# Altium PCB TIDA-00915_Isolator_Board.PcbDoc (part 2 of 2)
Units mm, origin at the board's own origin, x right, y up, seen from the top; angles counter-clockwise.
Board outline 80 x 46 mm, 4 copper layers (Top Layer, L2, L3, Bottom Layer), stack 0.8 mm thick; 132 components, 79 nets, 362 pads, 253 vias.
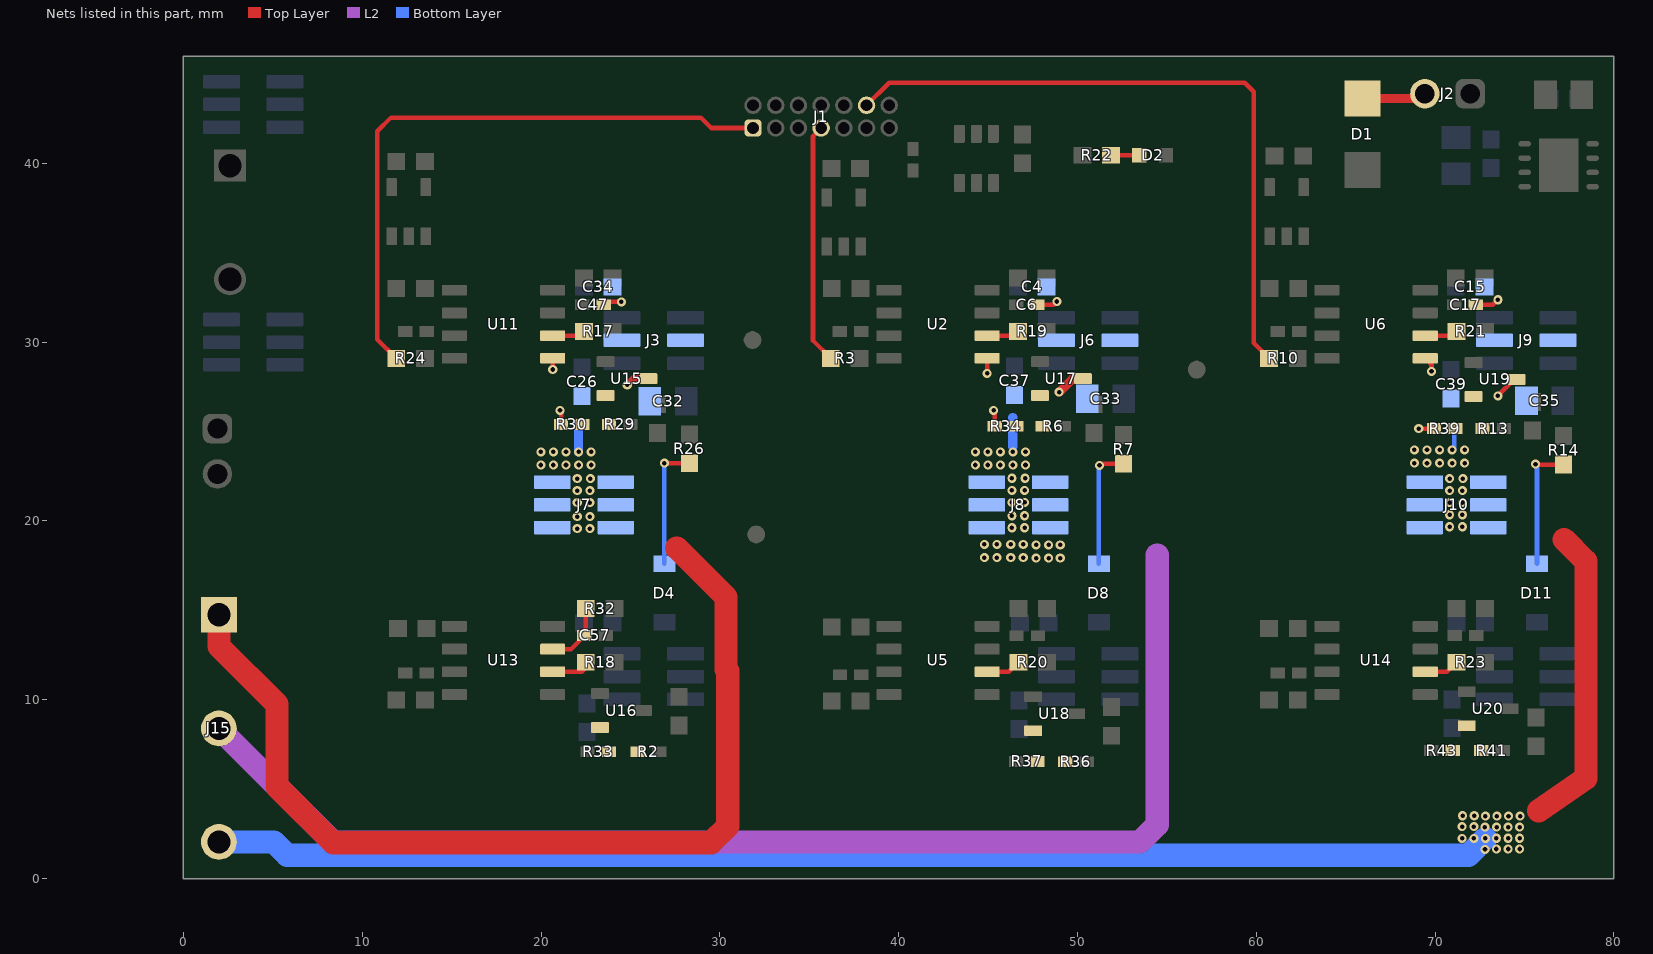
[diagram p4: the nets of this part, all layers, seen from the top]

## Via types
v1: diameter 0.508, hole 0.254, Top Layer to Bottom Layer, 248 vias
v2: diameter 0.5, hole 0.2, Top Layer to Bottom Layer, 5 vias

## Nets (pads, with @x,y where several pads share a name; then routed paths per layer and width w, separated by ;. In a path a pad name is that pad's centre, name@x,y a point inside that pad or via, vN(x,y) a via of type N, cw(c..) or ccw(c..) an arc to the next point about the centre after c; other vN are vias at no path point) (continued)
NetC57_1: C57.1 R32.1 U13.7 | length 3.6
  Top Layer w0.254: U13.7@20.65,12.835 21.672,12.835 22.5,13.663 R32.1@22.5,15.1
NetD1_2: D1.2 J2.2 | length 3.6
  Top Layer w0.508: D1.2@65.938,43.624 69.154,43.624 J2.2@69.43,43.9
NetD2_1: D2.1 R22.1 | length 1.6
  Top Layer w0.254: R22.1@51.879,40.456 D2.1@53.454,40.456
NetD4_1: D4.1 R26.1 | length 7
  Top Layer w0.254: v1(26.899,23.234) 26.905,23.228 R26.1@28.296,23.228
  Bottom Layer w0.254: D4.1@26.899,17.608 v1(26.899,23.234)
NetD8_1: D8.1 R7.1 | length 6.9
  Top Layer w0.254: v1(51.232,23.107) 51.327,23.203 R7.1@52.578,23.203
  Bottom Layer w0.254: D8.1@51.2,17.608 51.2,23.076 v1(51.232,23.107)
NetD11_1: D11.1 R14.1 | length 7.2
  Top Layer w0.254: v1@75.632,23.2 v1(75.616,23.184) ccw(c75.647,23.184) 75.647,23.152 R14.1@77.191,23.152
  Bottom Layer w0.254: v1(75.616,23.184) 75.7,23.099 D11.1@75.7,17.607
NetR2_1: R2.1 R33.2 U16.2
NetR6_1: R6.1 R34.2 U17.2
NetR13_1: R13.1 R39.2 U19.2
NetR17_1: R17.1 U11.6 | length 1.8
  Top Layer w0.254: U11.6@20.65,30.365 22.165,30.365 R17.1@22.4,30.6
NetR18_1: R18.1 U13.6 | length 2.4
  Top Layer w0.254: U13.6@20.65,11.565 22.265,11.565 R18.1@22.8,12.1
NetR19_1: R19.1 U2.6 | length 1.8
  Top Layer w0.254: U2.6@44.95,30.365 46.438,30.365 R19.1@46.673,30.6
NetR20_1: R20.1 U5.6 | length 2
  Top Layer w0.254: U5.6@44.95,11.565 46.165,11.565 R20.1@46.7,12.1
NetR21_1: R21.1 U6.6 | length 1.8
  Top Layer w0.254: U6.6@69.45,30.365 70.965,30.365 R21.1@71.2,30.6
NetR23_1: R23.1 U14.6 | length 2
  Top Layer w0.254: U14.6@69.45,11.565 70.665,11.565 R23.1@71.2,12.1
NetR29_1: R29.1 R30.2 U15.2
NetR36_1: R36.1 R37.2 U18.2
NetR41_1: R41.1 R43.2 U20.2
PHASEU: C26.2 C32.2 C34.2 C47.2 J3.3 J3.4 J7.1 J7.2 J7.3 J7.4 J7.5 J7.6 J15.1 R30.1 U11.5 U15.3 | length 60
  Top Layer w0.254: v1(20.65,28.474) U11.5@20.65,29.095 ; v1(21.057,26.187) 21.117,26.127 R30.1@21.117,25.4 ; C47.2@23.5,32.1 23.658,32.258 v1(24.486,32.258)
  Top Layer w0.4: v1(24.82,27.616) 25.169,27.965 U15.3@26,27.965
  Top Layer w1.3: J15.1@1.981,14.75 1.981,12.996 5.231,9.746 5.231,5.15 8.381,2 29.5,2 30.436,2.936 30.436,11.605 30.347,11.694 30.347,15.733 27.584,18.495
  Bottom Layer w0.508: v1(22.095,23.869) 22.095,25.473
  other v1: 22.022,19.577 22.733,19.577 22.022,20.25 22.733,20.25 22.022,21.025 22.733,21.025 22.022,21.698 22.733,21.698 22.022,22.371 22.758,22.371 19.99,23.133 20.691,23.133 21.393,23.133 22.095,23.133 22.796,23.133 19.99,23.869 20.691,23.869 21.393,23.869 22.796,23.869
PHASEV: C4.2 C6.2 C33.2 C37.2 J6.3 J6.4 J8.1 J8.2 J8.3 J8.4 J8.5 J8.6 J15.2 R34.1 U2.5 U17.3 | length 76.8
  Top Layer w0.254: U2.5@44.933,29.095 U2.5@44.95,29.095 v1(44.95,28.259) ; v1(45.314,26.187) 45.374,26.127 R34.1@45.374,25.298 ; C6.2@47.768,32.1 48.667,32.1 v1(48.844,32.277)
  Top Layer w0.5: v1(48.971,27.203) 49.733,27.965 U17.3@50.3,27.965
  L2 w1.3: J15.2@1.981,8.4 8.331,2.05 53.5,2.05 54.458,3.008 54.458,18.104
  Bottom Layer w0.508: 46.377,24.174 46.377,25.778
  other v1: 47.688,17.926 48.39,17.926 49.035,17.926 44.793,17.951 45.495,17.951 46.266,17.951 46.968,17.951 47.688,18.662 48.39,18.662 49.035,18.662 44.793,18.688 45.495,18.688 46.266,18.688 46.968,18.688 46.33,19.621 47.041,19.621 46.33,20.295 47.041,20.295 46.33,21.044 47.041,21.044 46.33,21.717 47.041,21.717 46.33,22.39 47.066,22.39 44.285,23.133 44.987,23.133 45.688,23.133 46.39,23.133 47.092,23.133 44.285,23.869 44.987,23.869 45.688,23.869 46.39,23.869 47.092,23.869
PHASEW: C15.2 C17.2 C35.2 C39.2 J9.3 J9.4 J10.1 J10.2 J10.3 J10.4 J10.5 J10.6 J15.3 R39.1 U6.5 U19.3 | length 94.2
  Top Layer w0.254: v1(69.088,25.171) R39.1@69.936,25.171 ; U6.5@69.45,29.095 69.799,28.746 v1(69.799,28.372) ; C17.2@72.279,32.1 73.233,32.1 v1(73.508,32.375) ; v1(73.508,27) 74.422,27.915 U19.3@74.555,27.915
  Top Layer w1.3: 75.8,3.8 78.435,5.607 78.435,17.748 77.216,18.967
  Bottom Layer w0.254: v1@71.079,23.971 71.079,25.124
  Bottom Layer w1.3: J15.3@1.981,2.05 5.05,2.05 5.8,1.3 71.87,1.3 v1(72.816,2.246)
  other v1: 72.791,1.637 73.432,1.656 74.082,1.656 74.732,1.656 71.516,2.246 72.166,2.246 73.432,2.256 74.082,2.256 74.732,2.256 72.786,2.881 73.436,2.881 74.082,2.881 74.732,2.881 71.516,2.907 72.166,2.907 72.812,3.491 73.462,3.491 74.107,3.491 74.757,3.491 71.542,3.516 72.192,3.516 70.815,19.678 71.526,19.678 70.815,20.352 71.526,20.352 70.815,21.025 71.526,21.025 70.815,21.698 71.526,21.698 70.815,22.371 71.552,22.371 68.847,23.241 69.548,23.241 70.25,23.241 70.952,23.241 71.653,23.241 68.847,23.978 69.548,23.978 70.25,23.978 70.952,23.978 71.653,23.978
Top_FET_U: J1.1 R24.1 | length 34.7
  Top Layer w0.254: R24.1@11.9,29.1 10.846,30.154 10.846,41.802 11.608,42.564 28.931,42.564 29.515,41.98 J1.1@31.852,41.98
Top_FET_V: J1.7 R3.1 | length 13.5
  Top Layer w0.254: J1.7@35.662,41.98 35.208,41.526 35.208,30.092 R3.1@36.2,29.1
Top_FET_W: J1.12 R10.1 | length 37.7
  Top Layer w0.254: J1.12@38.202,43.25 39.472,44.52 59.36,44.52 59.863,44.016 59.863,29.956 R10.1@60.719,29.1
pads on no net: FID1.1 FID2.1 FID3.1

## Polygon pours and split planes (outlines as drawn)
PHASEW on Bottom Layer "BOTTOM_LAYER_PHASEW_P072" (solid, remove dead copper, pour order 72): 68.783,24.835 ccw(c68.961,24.835) 68.961,24.657 77.47,24.657 ccw(c77.47,24.835) 77.648,24.835 77.622,25.47 77.622,34.055 ccw(c77.47,34.055) 77.47,34.207 69.113,34.207 ccw(c69.113,33.877) 68.783,33.877
PHASEV on Bottom Layer "BOTTOM_LAYER_PHASEV_P068" (solid, remove dead copper, pour order 68): 44.348,24.758 ccw(c44.526,24.758) 44.526,24.581 53.035,24.581 ccw(c53.035,24.758) 53.213,24.758 53.188,25.393 53.188,33.979 ccw(c53.035,33.979) 53.035,34.131 44.679,34.131 ccw(c44.679,33.801) 44.348,33.801
PHASEU on Bottom Layer "BOTTOM_LAYER_PHASEU_P066" (solid, remove dead copper, pour order 66): 20.168,24.809 ccw(c20.345,24.809) 20.345,24.631 28.854,24.631 ccw(c28.854,24.809) 29.032,24.809 29.007,25.444 29.007,34.029 ccw(c28.854,34.029) 28.854,34.182 20.498,34.182 ccw(c20.498,33.852) 20.168,33.852
PHASEW on Bottom Layer "BOTTOM_LAYER_PHASEW_P056" (solid, remove dead copper, pour order 56): 74.306,22.301 ccw(c74.061,22.301) 74.061,22.546 72.125,22.546 cw(c72.125,22.597) 72.074,22.597 72.074,24.248 ccw(c71.896,24.248) 71.896,24.426 68.721,24.426 ccw(c68.717,24.218) 68.509,24.222 68.509,19.672 ccw(c68.909,19.672) 68.909,19.272 74.109,19.272 ccw(c74.109,19.473) 74.309,19.473 74.309,22.267 ccw(c74.131,22.267)
PHASEV on Bottom Layer "BOTTOM_LAYER_PHASEV_P048" (solid, remove dead copper, pour order 48): 44.063,24.428 ccw(c44.063,24.205) 43.84,24.205 43.84,19.434 ccw(c43.997,19.438) 44.001,19.282 ccw(c44.079,19.675) 44.079,19.275 49.279,19.275 ccw(c49.279,19.475) 49.479,19.475 49.479,22.269 ccw(c49.302,22.269) 49.476,22.304 ccw(c49.231,22.304) 49.231,22.549 47.295,22.549 cw(c47.295,22.599) 47.244,22.599 47.244,24.25 ccw(c47.066,24.25) 47.066,24.428
PHASEU on Bottom Layer "BOTTOM_LAYER_PHASEU_P008" (solid, remove dead copper, pour order 8): 25.397,22.329 ccw(c25.152,22.329) 25.152,22.574 23.216,22.574 cw(c23.216,22.625) 23.165,22.625 23.165,24.276 ccw(c22.987,24.276) 22.987,24.454 19.812,24.454 ccw(c19.808,24.246) 19.6,24.25 19.6,19.7 ccw(c20,19.7) 20,19.3 25.199,19.3 ccw(c25.199,19.501) 25.4,19.501 25.4,22.295 ccw(c25.222,22.295)
HVBUS_RTN on Bottom Layer "BOTTOM_LAYER_HVBUS_RTN_P000" (solid, remove dead copper, pour order 0): 19.9,7.274 19.9,4.8 ccw(c20.1,4.8) 20.1,4.6 25.7,4.6 ccw(c25.7,5) 26.1,5 26.1,6.788 ccw(c25.903,6.8) 26.1,6.8 26.1,10.4 cw(c26.4,10.4) 26.4,10.7 28.7,10.7 ccw(c28.7,11) 29,11 29,14.9 ccw(c28.5,14.9) 28.5,15.4 23.3,15.4 cw(c23.3,15.7) 23,15.7 23,15.8 ccw(c22.9,15.8) 22.9,15.9 20.2,15.9 ccw(c20.2,15.6) 19.9,15.6 19.9,7.3 ccw(c20.609,7.3)
HVBUS_RTN on Bottom Layer "BOTTOM_LAYER_HVBUS_RTN_P036" (solid, remove dead copper, pour order 36): 44.157,3.847 ccw(c44.2,3.847) 44.2,3.804 50.004,3.804 ccw(c50.004,4.2) 50.4,4.2 50.4,10.57 cw(c50.657,10.57) 50.657,10.827 52.957,10.827 ccw(c52.957,11.127) 53.257,11.127 53.257,15.027 ccw(c52.757,15.027) 52.757,15.527 47.557,15.527 cw(c47.557,15.827) 47.257,15.827 47.257,15.927 ccw(c47.157,15.927) 47.157,16.027 44.457,16.027 ccw(c44.457,15.727) 44.157,15.727
5V on Bottom Layer "BOTTOM_LAYER_5V_P080" (solid, remove dead copper, pour order 80): 66.827,39.871 66.827,38.728 ccw(c67.119,38.741) 67.132,38.449 74.273,38.449 ccw(c74.273,38.855) 74.68,38.855 74.68,40.065 ccw(c74.597,40.065) 74.597,40.148 67.104,40.148 ccw(c67.104,39.871)
PHASEW on Bottom Layer "BOTTOM_LAYER_PHASEW_P086" (solid, remove dead copper, pour order 86): 76.179,4.567 ccw(c75.773,4.567) 75.773,4.974 70.795,4.974 ccw(c70.795,4.669) 70.49,4.669 70.49,1.722 ccw(c70.871,1.722) 70.871,1.341 75.824,1.341 ccw(c75.824,1.697) 76.179,1.697
HVBUS on Bottom Layer "BOTTOM_LAYER_HVBUS_P088" (solid, remove dead copper, pour order 88): 6.323,33.917 6.323,34.387 ccw(c6.02,34.387) 6.02,34.69 1.219,34.69 ccw(c1.219,34.436) 0.965,34.436 0.965,28.767 ccw(c1.313,28.772) 1.318,28.424 ccw(c1.397,28.822) 1.397,28.416 6.045,28.416 ccw(c6.045,28.695) 6.325,28.695 6.325,33.877 ccw(c5.918,33.877)
HVBUS_RTN on Bottom Layer "BOTTOM_LAYER_HVBUS_RTN_P090" (solid, remove dead copper, pour order 90): 6.399,44.255 6.399,44.725 ccw(c6.096,44.725) 6.096,45.028 1.295,45.028 ccw(c1.295,44.774) 1.041,44.774 1.041,39.105 ccw(c1.389,39.109) 1.394,38.762 ccw(c1.473,39.16) 1.473,38.754 6.121,38.754 ccw(c6.121,39.033) 6.401,39.033 6.401,44.215 ccw(c5.995,44.215)
GND on Bottom Layer "BOTTOM_LAYER_GND_P092" (solid, remove dead copper, pour order 92): 64,9.2 ccw(c64,9.5) 64.3,9.5 64.3,38.648 cw(c64.442,38.637) 64.452,38.779 65.557,38.779 ccw(c65.557,38.957) 65.735,38.957 65.735,40.735 cw(c66.4,40.735) 66.4,41.4 74.5,41.4 cw(c74.5,40.9) 75,40.9 75,38.6 ccw(c75.6,38.6) 75.6,38 79.1,38 ccw(c79.1,38.2) 79.3,38.2 79.3,44.8 ccw(c78.9,44.8) 78.9,45.2 11.9,45.2 ccw(c11.9,44.5) 11.2,44.5 11.2,25.8 cw(c10.9,25.8) 10.9,25.5 10,25.5 ccw(c10,25) 9.5,25 9.5,9.6 ccw(c9.9,9.6) 9.9,9.2 15.3,9.2 ccw(c15.3,9.5) 15.6,9.5 15.6,37.918 cw(c15.969,37.918) 15.969,38.287 33.245,38.287 cw(c33.245,38.011) 33.521,38.011 33.521,9.479 ccw(c33.9,9.479) 33.9,9.1 39.4,9.1 ccw(c39.4,9.5) 39.8,9.5 39.8,37.8 cw(c40.4,37.8) 40.4,38.4 58.087,38.4 cw(c58.087,38.072) 58.415,38.072 58.415,9.785 ccw(c59,9.785) 59,9.2
HVBUS_RTN on Bottom Layer "BOTTOM_LAYER_HVBUS_RTN_P096" (solid, remove dead copper, pour order 96): 68.7,15.7 cw(c69,15.7) 69,16 71.7,16 cw(c71.7,15.9) 71.8,15.9 71.8,15.8 ccw(c72.1,15.8) 72.1,15.5 77.3,15.5 cw(c77.3,15) 77.8,15 77.8,11.1 cw(c77.5,11.1) 77.5,10.8 75.2,10.8 ccw(c75.2,10.5) 74.9,10.5 74.9,6.9 cw(c74.7,6.9) 74.7,6.7 69.4,6.7 cw(c69.4,7.4) 68.7,7.4
12V on L3 "L3_12V_P054" (solid, remove dead copper, pour order 54): 70.307,6.393 ccw(c70.9,6.393) 70.9,5.8 76.2,5.8 ccw(c76.2,6.5) 76.9,6.5 76.9,14.528 ccw(c76.452,14.522) 76.447,14.97 ccw(c76.352,14.497) 76.352,14.979 70.637,14.979 ccw(c70.637,14.649) 70.307,14.649
12V on L3 "L3_12V_P038" (solid, remove dead copper, pour order 38): 46.024,1.976 ccw(c46.3,1.976) 46.3,1.7 52.2,1.7 ccw(c52.2,2) 52.5,2 52.5,14.899 ccw(c52.17,14.894) 52.164,15.224 ccw(c52.07,14.751) 52.07,15.233 46.354,15.233 ccw(c46.354,14.903) 46.024,14.903
12V on L3 "L3_12V_P040" (solid, remove dead copper, pour order 40): 22.115,6.9 ccw(c22.503,6.901) 22.504,6.513 ccw(c22.497,6.717) 22.522,6.514 28.034,6.514 ccw(c28.034,7.124) 28.644,7.124 28.644,14.49 ccw(c28.161,14.49) 28.161,14.973 22.445,14.973 ccw(c22.445,14.642) 22.115,14.642
5V on L3 "L3_5V_P082" (solid, pour order 82): 33.909,43.097 ccw(c34.239,43.097) 34.239,42.767 35.814,42.767 ccw(c35.814,43.097) 36.144,43.097 36.144,44.697 ccw(c36.017,44.697) 36.017,44.824 34.188,44.824 ccw(c34.188,44.545) 33.909,44.545
HVBUS_RTN on L3 "L3_HVBUS_RTN_P094" (solid, remove dead copper, pour order 94): 19.9,8 19.9,4.788 ccw(c20.088,4.788) 20.088,4.6 25.7,4.6 ccw(c25.7,5) 26.1,5 26.1,5.8 ccw(c26,5.8) 26,5.9 21.9,5.9 cw(c21.9,6.1) 21.7,6.1 21.7,8.2 ccw(c21.5,8.2) 21.5,8.4 20.3,8.4 ccw(c20.3,8)
5V_H_W on L2 "L2_5V_H_W_P074" (solid, remove dead copper, pour order 74): 69.151,34.048 68.897,34.048 ccw(c68.897,33.934) 68.783,33.934 68.783,24.799 ccw(c68.926,24.799) 68.926,24.657 76.339,24.657 ccw(c76.339,24.816) 76.498,24.816 76.498,27.534 ccw(c76.312,27.534) 76.312,27.721 74.049,27.721 cw(c74.049,27.915) 73.855,27.915 73.855,30.615 ccw(c73.562,30.612) 73.558,30.905 70.923,30.905 cw(c70.923,31.166) 70.663,31.166 70.663,33.922 ccw(c70.53,33.922) 70.53,34.055 69.215,34.055 ccw(c69.215,33.725)
5V_H_V on L2 "L2_5V_H_V_P070" (solid, remove dead copper, pour order 70): 51.885,27.464 ccw(c51.587,27.464) 51.587,27.762 49.61,27.762 cw(c49.61,27.97) 49.403,27.97 49.403,30.829 ccw(c49.251,30.829) 49.251,30.981 46.438,30.981 cw(c46.438,31.242) 46.177,31.242 46.177,33.998 ccw(c46.044,33.998) 46.044,34.131 44.729,34.131 ccw(c44.729,33.801) 44.399,33.801 44.399,24.79 ccw(c44.628,24.79) 44.628,24.562 51.581,24.562 ccw(c51.581,24.867) 51.885,24.867
5V_H_U on L2 "L2_5V_H_U_P064" (solid, remove dead copper, pour order 64): 20.168,24.774 ccw(c20.31,24.774) 20.31,24.631 26.631,24.631 ccw(c26.631,25.2) 27.2,25.2 27.2,28 ccw(c26.9,28) 26.9,28.3 25.4,28.3 cw(c25.386,28.514) 25.171,28.5 25.171,30.88 ccw(c25.019,30.88) 25.019,31.032 22.206,31.032 cw(c22.206,31.293) 21.946,31.293 21.946,34.049 ccw(c21.813,34.049) 21.813,34.182 20.498,34.182 ccw(c20.498,33.852) 20.168,33.852
5V_L_W on L2 "L2_5V_L_W_P052" (solid, remove dead copper, pour order 52): 69.105,15.405 68.822,15.405 ccw(c68.822,15.283) 68.7,15.283 68.7,7.148 ccw(c69.068,7.148) 69.068,6.78 76.147,6.78 ccw(c76.147,7.264) 76.632,7.264 76.632,10.922 ccw(c76.251,10.922) 76.251,11.303 72.454,11.303 cw(c72.454,11.589) 72.168,11.589 72.168,15.227 ccw(c71.984,15.227) 71.984,15.411 69.164,15.411 ccw(c69.164,15.106)
5V_L_U on L2 "L2_5V_L_U_P004" (solid, remove dead copper, pour order 4): 19.9,8.72 ccw(c20.22,8.72) 20.22,8.4 22.85,8.4 cw(c22.85,8.2) 23.05,8.2 23.05,6.8 ccw(c23.3,6.8) 23.3,6.55 27.95,6.55 ccw(c27.95,6.9) 28.3,6.9 28.3,11.3 ccw(c28.1,11.3) 28.1,11.5 23.525,11.5 cw(c23.525,11.625) 23.4,11.625 23.4,15.7 ccw(c23.2,15.7) 23.2,15.9 20.2,15.9 ccw(c20.2,15.6) 19.9,15.6
3V3 on L2 "L2_3V3_P010" (solid, pour order 10): 58.42,22.497 ccw(c59.029,22.497) 59.029,21.888 60.96,21.888 cw(c60.96,21.177) 61.671,21.177 61.671,15.143 ccw(c62.381,15.156) 62.394,14.446 63.373,14.446 ccw(c63.373,15.03) 63.957,15.03 63.957,38.215 cw(c64.344,38.215) 64.344,38.601 65.405,38.601 ccw(c65.392,38.944) 65.735,38.957 65.735,40.684 cw(c65.989,40.684) 65.989,40.938 70.409,40.938 cw(c70.409,40.659) 70.688,40.659 70.688,39.059 ccw(c71.145,39.059) 71.145,38.601 79.258,38.601 ccw(c79.258,38.795) 79.451,38.795 79.451,45.002 ccw(c79.299,45.002) 79.299,45.155 9.627,45.155 ccw(c9.627,44.977) 9.449,44.977 9.449,44.306 9.449,42.214 ccw(c9.872,42.21) 9.449,42.208 9.449,16.021 9.449,14.446 ccw(c10.262,14.446) 10.262,13.633 15.043,13.633 ccw(c15.043,14.262) 15.672,14.262 15.672,37.925 cw(c16.041,37.925) 16.041,38.294 cw(c16.1,38.003) 16.1,38.3 33.169,38.3 cw(c33.169,37.941) 33.528,37.941 33.528,14.09 ccw(c34.214,14.09) 34.214,13.405 39.192,13.405 ccw(c39.19,14.215) 40,14.217 40,38.1 cw(c40.2,38.1) 40.2,38.3 58.137,38.3 cw(c58.137,38.017) 58.42,38.017
5V_L_V on L2 "L2_5V_L_V_P042" (solid, remove dead copper, pour order 42): 51.664,5.69 ccw(c51.664,5.994) 51.968,5.994 51.968,11.252 ccw(c51.689,11.252) 51.689,11.532 47.867,11.532 cw(c47.867,11.69) 47.708,11.69 47.708,15.328 ccw(c47.523,15.328) 47.523,15.513 44.704,15.513 ccw(c44.704,15.209) 44.645,15.507 ccw(c44.641,15.062) 44.196,15.065 44.196,6.198 ccw(c44.704,6.198) 44.704,5.69
PHASEV on L2 "L2_PHASEV_P046" (solid, remove dead copper, pour order 46): 44.171,17.907 ccw(c44.527,17.907) 44.527,17.551 44.806,17.552 45.716,17.553 ccw(c45.775,17.847) 45.775,17.548 54.614,17.548 ccw(c54.614,17.827) 54.669,17.553 ccw(c54.672,17.999) 55.118,17.996 55.118,19.431 ccw(c54.635,19.431) 54.635,19.914 49.784,19.914 cw(c49.784,20.066) 49.632,20.066 49.632,22.443 ccw(c49.5,22.443) 49.5,22.574 44.545,22.574 ccw(c44.545,22.2) 44.171,22.2
NetR41_1 on Top Layer "TOP_LAYER_NETR41_1_P110" (solid, remove dead copper, pour order 110): 71.612,8.757 ccw(c71.612,8.478) 71.333,8.478 71.323,8.452 71.323,7.493 cw(c71.196,7.493) 71.196,7.366 70.887,7.366 ccw(c70.887,7.163) 70.683,7.163 70.683,7.013 ccw(c70.833,7.013) 70.833,6.863 72.68,6.863 ccw(c72.68,7.01) 72.827,7.01 72.827,7.362 ccw(c72.727,7.362) 72.727,7.463 72.446,7.463 cw(c72.446,7.722) 72.187,7.722 72.187,8.539 ccw(c71.969,8.539) 71.969,8.757
NetR13_1 on Top Layer "TOP_LAYER_NETR13_1_P108" (solid, remove dead copper, pour order 108): 70.663,25.451 70.663,24.816 70.739,24.74 73.076,24.74 73.127,24.79 73.127,25.527 73.076,25.578 72.949,25.578 72.746,25.781 72.746,27.254 72.644,27.356 71.704,27.356 71.628,27.28 71.628,25.908 71.323,25.603 70.815,25.603
PHASEW on Top Layer "TOP_LAYER_PHASEW_P058" (solid, remove dead copper, pour order 58): 68.523,18.395 ccw(c68.91,18.395) 68.91,18.009 77.953,18.009 ccw(c77.953,18.313) 78.257,18.313 78.257,20.676 ccw(c77.953,20.676) 77.953,20.98 74.574,20.98 cw(c74.589,21.246) 74.323,21.26 74.323,22.298 ccw(c74.124,22.298) 74.124,22.498 72.317,22.498 cw(c72.317,22.701) 72.114,22.701 72.118,23.042 cw(c72.317,23.082) 72.114,23.082 72.114,24.157 ccw(c71.893,24.157) 71.893,24.377 68.727,24.377 ccw(c68.727,24.174) 68.523,24.174
PHASEV on Top Layer "TOP_LAYER_PHASEV_P050" (solid, remove dead copper, pour order 50): 54.445,17.551 ccw(c54.445,17.818) 54.711,17.818 54.711,20.676 ccw(c54.331,20.676) 54.331,21.057 49.962,21.057 cw(c49.963,21.36) 49.66,21.361 49.66,22.375 ccw(c49.461,22.375) 49.461,22.574 47.653,22.574 cw(c47.653,22.777) 47.45,22.777 47.454,23.119 cw(c47.653,23.158) 47.45,23.158 47.45,24.233 ccw(c47.23,24.233) 47.23,24.454 44.063,24.454 ccw(c44.063,24.25) 43.86,24.25 43.86,18.167 ccw(c44.475,18.167) 44.475,17.551
PHASEU on Top Layer "TOP_LAYER_PHASEU_P006" (solid, remove dead copper, pour order 6): 19.604,20.961 19.604,17.81 ccw(c19.837,17.81) 19.837,17.577 28.067,17.577 ccw(c28.067,17.907) 28.397,17.907 28.397,20.244 ccw(c27.889,20.244) 27.889,20.752 25.959,20.752 cw(c25.959,21.311) 25.4,21.311 25.4,22.375 ccw(c25.201,22.375) 25.201,22.574 23.393,22.574 cw(c23.393,22.777) 23.19,22.777 23.194,23.119 cw(c23.393,23.158) 23.19,23.158 23.19,24.233 ccw(c22.97,24.233) 22.97,24.454 19.803,24.454 ccw(c19.803,24.25) 19.6,24.25 19.6,21 ccw(c19.8,21)
GND on Top Layer "TOP_LAYER_GND_P018" (solid, remove dead copper, pour order 18): 12.282,17.991 13.081,17.191 13.081,15.57 12.5,14.989 12.5,13.7 cw(c12.301,13.676) 12.406,13.506 12.294,13.437 11.506,13.437 cw(c11.595,13.932) 11.1,13.843 11.1,18.923 cw(c11.147,18.923) 11.147,18.97 12.221,18.97 cw(c12.222,18.91) 12.282,18.909
3V3 on Top Layer "TOP_LAYER_3V3_P030" (solid, remove dead copper, pour order 30): 79.01,38.37 ccw(c79.01,38.56) 79.2,38.56 79.2,44.212 ccw(c78.995,44.21) 78.994,44.415 77.983,44.415 ccw(c77.983,44.124) 77.692,44.124 77.692,42.852 cw(c77.514,42.852) 77.514,42.675 75.571,42.675 ccw(c75.571,42.637) 75.533,42.637 75.533,38.606 ccw(c75.768,38.609) 75.77,38.374 ccw(c75.813,38.588) 75.813,38.37
5V on Top Layer "TOP_LAYER_5V_P078" (solid, remove dead copper, pour order 78): 74.828,40.43 64.745,40.43 ccw(c64.745,40.024) 64.338,40.024 64.338,38.779 ccw(c64.77,38.779) 64.77,38.347 74.981,38.347 ccw(c74.981,38.678) 75.311,38.678 75.311,39.948 ccw(c74.828,39.948)
PHASEW on Top Layer "TOP_LAYER_PHASEW_P084" (solid, remove dead copper, pour order 84): 76.179,4.542 ccw(c75.773,4.542) 75.773,4.948 70.795,4.948 ccw(c70.795,4.643) 70.49,4.643 70.49,1.697 ccw(c70.871,1.697) 70.871,1.316 75.824,1.316 ccw(c75.824,1.672) 76.179,1.672
NetR2_1 on Top Layer "TOP_LAYER_NETR2_1_P100" (solid, remove dead copper, pour order 100): 22.865,8.58 ccw(c22.865,8.523) 22.808,8.523 22.808,8.148 ccw(c22.908,8.148) 22.908,8.048 23.35,8.048 cw(c23.35,7.891) 23.508,7.891 23.508,6.973 ccw(c23.658,6.973) 23.658,6.823 25.458,6.823 ccw(c25.458,6.923) 25.558,6.923 25.558,7.673 ccw(c25.408,7.673) 25.408,7.823 24.308,7.823 cw(c24.308,8.223) 23.908,8.223 23.908,8.42 ccw(c23.747,8.42) 23.747,8.58
NetR29_1 on Top Layer "TOP_LAYER_NETR29_1_P098" (solid, remove dead copper, pour order 98): 23.407,27.217 23.128,27.217 ccw(c23.128,27.178) 23.089,27.178 23.089,25.933 cw(c22.936,25.933) 22.936,25.781 22.204,25.781 ccw(c22.204,25.7) 22.123,25.7 22.123,25.144 ccw(c22.167,25.144) 22.167,25.101 23.851,25.101 ccw(c23.851,25.3) 24.05,25.3 24.05,27.158 ccw(c23.986,27.158) 23.986,27.222 23.457,27.222 ccw(c23.457,26.965)
NetR6_1 on Top Layer "TOP_LAYER_NETR6_1_P102" (solid, remove dead copper, pour order 102): 47.657,27.217 47.41,27.217 ccw(c47.41,27.178) 47.371,27.178 47.371,25.664 cw(c47.348,25.664) 47.348,25.641 cw(c47.224,25.826) 47.224,25.603 46.507,25.603 ccw(c46.507,25.425) 46.33,25.425 46.33,25.093 ccw(c46.424,25.093) 46.424,24.999 48.144,24.999 ccw(c48.144,25.146) 48.291,25.146 48.291,27.222 47.707,27.222 ccw(c47.707,26.962)
NetR36_1 on Top Layer "TOP_LAYER_NETR36_1_P106" (solid, remove dead copper, pour order 106): 47.6,8.477 ccw(c47.6,8.325) 47.447,8.325 47.447,6.325 ccw(c47.518,6.325) 47.518,6.254 49.465,6.254 ccw(c49.465,6.35) 49.561,6.35 49.561,6.979 ccw(c49.479,6.979) 49.479,7.061 48.235,7.061 cw(c48.235,7.163) 48.133,7.163 48.133,8.247 ccw(c47.903,8.247) 47.903,8.477
3V3 on Top Layer "TOP_LAYER_3V3_P112" (solid, remove dead copper, pour order 112): 15.215,18.923 15.492,18.646 15.492,15.776 15.951,15.342 15.951,13.868 15.875,13.792 14.453,13.792 14.148,13.487 13.106,13.487 13.081,13.513 13.081,14.503 cw(c13.157,14.503) 13.157,14.58 13.386,14.58 13.767,14.961 13.767,17.526 13.31,17.983 12.802,17.983 12.751,18.034 12.751,18.974 cw(c12.852,18.974) 12.852,19.075 14.148,19.075 14.3,18.923
3V3 on Top Layer "TOP_LAYER_3V3_P114" (solid, remove dead copper, pour order 114): 39.473,18.988 39.75,18.711 39.75,15.841 40.21,15.407 40.21,13.933 40.134,13.857 38.711,13.857 38.406,13.552 37.365,13.552 37.34,13.578 37.34,14.568 cw(c37.416,14.568) 37.416,14.645 37.644,14.645 38.025,15.026 38.025,17.591 37.568,18.048 37.06,18.048 37.009,18.099 37.009,19.039 cw(c37.111,19.039) 37.111,19.14 38.406,19.14 38.559,18.988
GND on Top Layer "TOP_LAYER_GND_P116" (solid, remove dead copper, pour order 116): 36.54,18.056 37.34,17.256 37.34,15.635 36.759,15.054 36.759,13.765 cw(c36.56,13.741) 36.665,13.571 36.553,13.502 35.765,13.502 cw(c35.854,13.997) 35.358,13.908 35.358,18.988 cw(c35.405,18.988) 35.405,19.035 36.48,19.035 cw(c36.48,18.975) 36.54,18.974
3V3 on Top Layer "TOP_LAYER_3V3_P118" (solid, remove dead copper, pour order 118): 63.933,18.923 64.211,18.646 64.211,15.776 64.67,15.342 64.67,13.868 64.594,13.792 63.171,13.792 62.867,13.487 61.825,13.487 61.8,13.513 61.8,14.503 cw(c61.876,14.503) 61.876,14.58 62.105,14.58 62.486,14.961 62.486,17.526 62.028,17.983 61.52,17.983 61.47,18.034 61.47,18.974 cw(c61.571,18.974) 61.571,19.075 62.867,19.075 63.019,18.923
GND on Top Layer "TOP_LAYER_GND_P120" (solid, remove dead copper, pour order 120): 61.001,17.991 61.8,17.191 61.8,15.57 61.219,14.989 61.219,13.7 cw(c61.02,13.676) 61.125,13.506 61.013,13.437 60.225,13.437 cw(c60.314,13.932) 59.819,13.843 59.819,18.923 cw(c59.865,18.923) 59.865,18.97 60.94,18.97 cw(c60.94,18.91) 61.001,18.909

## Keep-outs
Keep-Out Layer:
  text ".Layer_Name" at -10.744,-50.286 h1.52

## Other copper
Top Layer:
  text ".Layer_Name" at -10.744,-50.286 h1.52
L2:
  text "'.Layer_Name'" at -10.744,-50.286 h1.52
L3:
  text "'.Layer_Name'" at -10.744,-50.286 h1.52
Bottom Layer:
  text ".Layer_Name" at -10.744,-50.286 h1.52

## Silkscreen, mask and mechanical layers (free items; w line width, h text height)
Top Overlay:
  lines w0.152: 22.073,8.56 22.428,8.204 22.428,7.849
  lines w0.254: 5.994,22.377 7.925,22.377 ; 6.96,21.488 6.96,23.216 ; 7.818,32.839 9.748,32.839 ; 8.783,31.95 8.783,33.677 ; 68.174,39.776 70.104,39.776 ; 69.139,38.887 69.139,40.615
  text "400V, 4A DC" at 7.874,42.647 h1.85
  text "5V, 0.2A DC" at 67.285,36.246 h1.85
  text "12V, 0.2A DC" at 5.664,24.79 h1.85
  text "U" at 7.264,14.402 h1.85
  text "V" at 7.493,7.899 h1.85
  text "200V RMS" at 6.909,4.318 h1.85
  text "W" at 7.341,1.499 h1.85
  text ".Layer_Name" at -10.744,-50.286 h1.52
Bottom Overlay:
  text ".Layer_Name" at -10.744,-50.286 h1.52
Top Paste:
  text ".Layer_Name" at -10.744,-50.286 h1.52
Bottom Paste:
  text ".Layer_Name" at -10.744,-50.286 h1.52
Top Solder:
  text ".Layer_Name" at -10.744,-50.286 h1.52
  text ".Layer_Name" at -10.744,-50.286 h1.52
Bottom Solder:
  text ".Layer_Name" at -10.744,-50.286 h1.52
Drill Guide:
  text ".Layer_Name" at -10.744,-50.286 h1.52
M1 Board Outline:
  the board outline again, w0.254
M2 Board Dimensions:
  rectangle: -25.4,-35.465 -22.225,-32.29
  rectangle: -22.225,-38.64 -12.7,-35.465
  lines w0.178: -25.4,-35.465 0,-35.465 ; -22.225,-38.64 -22.225,-32.29 ; -19.05,-38.64 -19.05,-32.29 ; -12.7,-38.64 -12.7,-32.29 ; -6.35,-38.64 -6.35,-32.29 ; -25.4,-38.64 0,-38.64 0,-32.29 -25.4,-32.29 -25.4,-38.64
M3 3D STEP Top:
  text ".Layer_Name" at -10.744,-50.286 h1.52
M4 3D STEP Bottom:
  text ".Layer_Name" at -10.744,-50.286 h1.52
M5 Assembly Top:
  lines w0.254: -32.817,-52.106 134.823,-52.106 ; -32.817,-46.942 134.874,-46.942 ; -32.817,-41.777 -32.817,-57.271 68.91,-57.271 134.874,-57.271 134.874,-41.777 -32.804,-41.777 -32.804,-57.271 7.214,-57.271 ; 29.794,-57.271 29.794,-41.777 ; 61.976,-46.942 61.976,-41.777 ; 83.312,-46.942 83.312,-41.777 ; 99.111,-57.436 99.111,-52.284
  text "COMPONENTS MARKED 'DNP' SHOULD NOT BE POPULATED." at 3.899,-36.57 h1.52
  text "ASSEMBLY VARIANT:" at 3.886,-39.504 h1.52
  text ".VariantName" at 30.201,-39.504 h1.52
  text "PCB VIEWED FROM TOP SIDE" at -31.204,-45.134 h1.52
  text "BOARD #:" at 31.699,-45.134 h1.52
  text ".PRJ_Number" at 45.555,-45.134 h1.52
  text "REV:" at 67.005,-45.134 h1.52
  text ".PCB_Rev" at 74.409,-45.134 h1.52
  text "SVN REV:" at 88.29,-45.134 h1.52
  text ".VersionControl_RevNumber" at 101.143,-45.134 h1.52
  text "TID #:" at 31.699,-50.299 h1.52
  text ".TID" at 45.555,-50.299 h1.52
  text "PLOT NAME =" at -31.204,-55.514 h1.52
  text ".plot_File_Name" at -10.744,-55.514 h1.52
  text "GENERATED    :" at 31.75,-55.514 h1.52
  text ".Print_Date" at 53.835,-55.514 h1.52
  text ".Print_Time" at 72.352,-55.514 h1.52
  text "TEXAS INSTRUMENTS" at 104.47,-55.514 h1.52
M6 Assembly Bottom:
  lines w0.254: -32.829,-46.954 134.861,-46.954 ; -32.779,-52.119 134.861,-52.119 ; 2.934,-57.449 2.934,-52.297 ; 18.732,-46.954 18.732,-41.79 ; 40.069,-46.954 40.069,-41.79 ; 72.25,-57.284 72.25,-41.79 ; 94.831,-57.284 134.849,-57.284 134.849,-41.79 -32.829,-41.79 -32.829,-57.284 33.134,-57.284 134.861,-57.284 134.861,-41.79
  text "COMPONENTS MARKED 'DNP' SHOULD NOT BE POPULATED." at 129.591,-36.557 h1.52
  text ".VariantName" at 103.073,-39.504 h1.52
  text "ASSEMBLY VARIANT:" at 129.464,-39.504 h1.52
  text ".VersionControl_RevNumber" at 0.902,-45.147 h1.52
  text "SVN REV:" at 13.754,-45.147 h1.52
  text ".PCB_Rev" at 27.635,-45.147 h1.52
  text "REV:" at 35.039,-45.147 h1.52
  text ".PRJ_Number" at 56.49,-45.147 h1.52
  text "BOARD #:" at 70.345,-45.147 h1.52
  text "PCB VIEWED FROM BOTTOM SIDE" at 133.248,-45.147 h1.52
  text ".TID" at 56.49,-50.311 h1.52
  text "TID #:" at 70.345,-50.311 h1.52
  text "TEXAS INSTRUMENTS" at -2.426,-55.527 h1.52
  text ".Print_Time" at 29.693,-55.527 h1.52
  text ".Print_Date" at 48.209,-55.527 h1.52
  text "GENERATED    :" at 70.294,-55.527 h1.52
  text ".plot_File_Name" at 112.789,-55.527 h1.52
  text "PLOT NAME =" at 133.248,-55.527 h1.52
M9 Title Sheet:
  drawing of 57 lines, arcs and shapes, not listed
  text "1" at -6.608,175.647 h1.78
  text "2" at 56.782,175.647 h1.78
  text "3" at 120.011,175.647 h1.78
  text "4" at 183.68,175.647 h1.78
  text "5" at 247.155,175.647 h1.78
  text "6" at 310.782,175.647 h1.78
  text "A" at -35.979,146.615 h1.78
  text "A" at 339.941,146.615 h1.78
  text "B" at -35.979,86.163 h1.78
  text "B" at 339.941,86.163 h1.78
  text "C" at -35.979,25.838 h1.78
  text "C" at 339.941,25.838 h1.78
  text "PROJECT TITLE:" at 262.725,-21.431 h1.14
  text ".PRJ_Title" at 263.995,-24.818 h1.78
  text "DESIGNED FOR:" at 262.725,-29.077 h1.14
  text ".PRJ_Customer" at 263.995,-32.633 h1.78
  text "D" at -35.979,-34.36 h1.78
  text "D" at 339.941,-34.36 h1.78
  text "FILE NAME:" at 262.725,-36.697 h1.14
  text ".PCB_File_Name_No_Path" at 263.995,-39.745 h1.78
  text "Texas Instruments (TI) and/or its licensors do not warrant the accuracy or completeness of this specification" at 136.5,-43.856 h1.14
  text "ENGINEER:" at 262.725,-44.063 h1.14
  text "LAYOUT BY:" at 300.952,-44.063 h1.14
  text "or any information contained therein. TI and/or its licensors do not warrant that this design will meet" at 135.357,-46.717 h1.14
  text ".PRJ_Engineer" at 263.995,-48 h1.78
  text ".PCB_Layout" at 302.235,-48 h1.78
  text "the specifications, will be suitable for your application or fit for any particular purpose, or will operate in" at 135.357,-49.579 h1.14
  text "ALTIUM DESIGNER VERSION:" at 300.952,-51.937 h1.14
  text "an implementation. TI and/or its licensors do not warrant that the design is production worthy. You should" at 135.357,-52.441 h1.14
  text "completely validate and test your design implementation to confirm the system functionality for your application." at 136.5,-55.302 h1.14
  text ".print_Scale" at 263.995,-55.323 h1.78
  text ".Application_BuildNumber" at 302.235,-55.323 h1.78
  text "1" at -6.608,-60.573 h1.78
  text "2" at 56.782,-60.573 h1.78
  text "3" at 120.011,-60.573 h1.78
  text "4" at 183.68,-60.573 h1.78
  text "5" at 247.155,-60.573 h1.78
  text "6" at 310.782,-60.573 h1.78
M10 Fab Notes:
  drawing of 189 lines, arcs and shapes, not listed
  text "DESIGN INFORMATION" at 289.103,132.967 h1.52
  text "MIN. TRACK WIDTH:" at 272.731,129.611 h1.52
  text "8" at 300.576,129.611 h1.52
  text "MIL" at 304.507,129.611 h1.52
  text "MIN. CLEARANCE:" at 272.731,126.458 h1.52
  text "0.2" at 299.052,126.458 h1.52
  text "mm" at 304.507,126.458 h1.52
  text "MIN. VIA PAD SIZE:" at 272.731,123.305 h1.52
  text "24" at 299.814,123.305 h1.52
  text "MIL" at 304.507,123.305 h1.52
  text "0.05mm (2MIL)" at 290.384,120.006 h1.52
  text "MINIMUM ANNULAR RING" at 264.369,119.797 h1.52
  text "EXTERNAL" at 308.368,119.797 h1.52
  text "PER" at 269.449,117 h1.52
  text "IPC-D-275 CLASS 2 LEVEL C" at 275.037,117 h1.52
  text "MIL, HOLES" at 312.838,114.448 h1.52
  text "+/-" at 302.87,114.229 h1.52
  text "+/-" at 324.561,114.229 h1.52
  text "REGISTRATION TOLERANCES:" at 264.369,114.202 h1.52
  text "METAL" at 294.843,114.202 h1.52
  text "5" at 309.479,114.203 h1.52
  text "3" at 330.637,114.203 h1.52
  text "MIL" at 333.59,114.202 h1.52
  text "HOLE SIZE TOLERANCE (UNLESS OTHERWISE SPECIFIED):" at 264.369,111.705 h1.52
  text "+/-" at 324.561,111.632 h1.52
  text "3" at 330.637,111.605 h1.52
  text "MIL" at 333.59,111.605 h1.52
  text "MATERIAL:" at 262.47,108.109 h1.52
  text "FR-4 High Tg" at 287.526,104.844 h1.52
  text "X" at 283.857,104.642 h1.52
  text "FR-408" at 273.163,104.527 h1.52
  text "OTHER" at 310.958,104.527 h1.52
  text "62 MIL (1.6mm) +/-10%" at 281.294,100.894 h1.52
  text "X" at 278.243,100.832 h1.52
  text "THICKNESS:" at 264.369,100.685 h1.52
  text "OTHER" at 313.93,100.685 h1.52
  text "TOLERANCE:" at 264.369,97.172 h1.52
  text "X" at 285.914,97.172 h1.52
  text "ANSI IPC-6012 TYPE 3 CLASS 2" at 290.436,97.172 h1.52
  text "OTHER +/-" at 290.435,93.509 h1.52
  text "BOW & TWIST:" at 264.369,89.822 h1.52
  text "X" at 285.914,89.822 h1.52
  text "ANSI IPC-6012 TYPE 3 CLASS 2" at 290.436,89.822 h1.52
  text "OTHER +/-" at 290.435,86.096 h1.52
  text "DRILLING:" at 262.47,82.778 h1.52
  text "NC_DRILL FILES" at 307.199,80.106 h1.52
  text "REFERENCE:" at 264.369,80.006 h1.52
  text "X" at 281.063,80.004 h1.52
  text "AS SHOWN" at 285.584,80.006 h1.52
  text "X" at 303.948,80.006 h1.52
  text "OTHER" at 314.768,76.393 h1.52
  text "PTH COPPER THICKNESS:" at 264.361,76.303 h1.52
  text "X" at 293.297,76.303 h1.52
  text "20-30 um" at 296.548,76.303 h1.52
  text "BOARD FINISH:" at 262.47,72.554 h1.52
  text "SILKSCREEN:" at 266.412,69.757 h1.52
  text "X" at 290.74,69.757 h1.52
  text "TOP" at 293.712,69.757 h1.52
  text "X" at 303.694,69.757 h1.52
  text "BOTTOM" at 306.691,69.757 h1.52
  text "SILKSCREEN COLOR:" at 266.412,65.815 h1.52
  text "X" at 290.715,65.815 h1.52
  text "WHITE" at 293.712,65.815 h1.52
  text "OTHER" at 306.691,65.815 h1.52
  text "X" at 294.042,62.172 h1.52
  text "GREEN" at 297.039,62.172 h1.52
  text "OTHER" at 312.736,62.172 h1.52
  text "SOLDER RESIST COLOR:" at 266.412,61.997 h1.52
  text "X" at 294.042,58.254 h1.52
  text "MATTE" at 297.039,58.254 h1.52
  text "SEMI-GLOSS" at 312.725,58.237 h1.52
  text "IMMERSION GOLD (ENIG)" at 289.419,53.865 h1.52
  text "ENEPIG" at 323.393,53.682 h1.52
  text "SURFACE FINISH:" at 262.47,53.656 h1.52
  text "X" at 284.898,53.656 h1.52
  text "IMM. TIN/SILVER OR EQUIV" at 270.84,50.169 h1.52
  text "OTHER" at 307.199,50.069 h1.52
  text "ARRAY/PANEL:" at 262.47,46.122 h1.52
  text "CUT AND TRIM PER M1 BOARD OUTLINE" at 289.419,45.913 h1.52
  text "N.C. ROUTE" at 289.419,42.46 h1.52
  text "X" at 306.895,42.46 h1.52
  text "V. SCORE" at 311.416,42.46 h1.52
  text "CERTIFICATION:" at 262.47,39.18 h1.52
  text "MATERIALS AND WORKMANSHIP FOR ALL PCBS" at 280.885,39.18 h1.52
  text "TO MEET OR EXCEED THE REQUIREMENTS OF:" at 280.885,36.791 h1.52
  text "X" at 271.678,33.523 h1.52
  text "ANSI IPC-A-600F CLASS ->" at 274.929,33.523 h1.52
  text "X" at 316.788,33.523 h1.52
  text "2" at 319.582,33.523 h1.52
  text "1" at 311.581,33.485 h1.52
  text "3" at 328.573,33.485 h1.52
  text "X" at 292.302,29.772 h1.52
  text "RoHS" at 295.553,29.772 h1.52
  text "OTHER" at 311.921,29.772 h1.52
  text "PER ORDER" at 322.007,29.772 h1.52
  text "ALL BOARDS MUST MEET OR EXCEED UL94-V0 REQUIREMENTS." at 263.169,25.865 h1.52
  text "PCB MUST BEAR THE UL94V-0 UL REGISTERED MATERIAL ID NUMBER" at 263.169,22.917 h1.52
  text "ADDITIONAL REQUIREMENTS:" at 262.47,18.614 h1.52
  text "MICROSECTION:" at 264.369,15.893 h1.52
  text "YES" at 287.375,15.893 h1.52
  text "REQUIRED" at 309.257,12.227 h1.52
  text "BARE BOARD ELEC. TEST:" at 264.369,12.154 h1.52
  text "NONE" at 297.535,12.154 h1.52
  text "X" at 306.26,12.154 h1.52
  text "PER ORDER" at 324.293,12.154 h1.52
  text "NOTE:" at 109.357,11.904 h1.52
  text "1)THIS IS NOT AN IMPEDANCE CONTROLLED BOARD." at 107.445,8.322 h1.52
  text "XX MIL VIAS REQUIRE NON-CONDUCTIVE FILL AND PLANARIZE" at 268.64,6.948 h1.5
  text "2)ALL VIAS ARE NONTENTED." at 107.276,5.4 h1.52
  text "XX MIL VIAS REQUIRE CONDUCTIVE FILL AND PLANARIZE" at 268.843,4.307 h1.52
  text "3)SELECTION OF DIELECRIC THICKNESS IS UP TO FAB VENDOR." at 107.376,2.5 h1.52
  text "OUTER XX MIL TRACES REQUIRE 50 OHM SINGLE-ENDED IMPEDANCE" at 268.818,0.157 h1.47
  text "4)COPPER THICKNESS SHOULD BE 2 OZ FOR INTERNAL AND EXTERNAL LAYERS." at 106.849,-0.473 h1.52
  text "LAYER 2 & 3 (INNER LAYERS) XX MIL WIDE, XX MIL SPACE / TRACES REQUIRE 100 OHM DIFFERENTIAL IMPEDANCE" at 268.615,-5.83 h1.52
M11 Gerber Information:
  lines w0.254: -32.817,-52.106 134.823,-52.106 ; -32.817,-46.942 134.874,-46.942 ; -32.817,-41.777 -32.817,-57.271 68.91,-57.271 134.874,-57.271 134.874,-41.777 -32.804,-41.777 -32.804,-57.271 7.214,-57.271 ; 29.794,-57.271 29.794,-41.777 ; 61.976,-46.942 61.976,-41.777 ; 83.312,-46.942 83.312,-41.777 ; 99.111,-57.436 99.111,-52.284
  text "ALL ARTWORK VIEWED FROM TOP SIDE" at -31.204,-45.134 h1.52
  text "BOARD #:" at 31.699,-45.134 h1.52
  text ".PRJ_Number" at 45.555,-45.134 h1.52
  text "REV:" at 67.005,-45.134 h1.52
  text ".PCB_Rev" at 74.409,-45.134 h1.52
  text "SVN REV:" at 88.29,-45.134 h1.52
  text ".VersionControl_RevNumber" at 101.143,-45.134 h1.52
  text "LAYER NAME =" at -31.204,-50.286 h1.52
  text "TID #:" at 31.699,-50.299 h1.52
  text ".TID" at 45.555,-50.299 h1.52
  text "PLOT NAME =" at -31.204,-55.514 h1.52
  text ".plot_File_Name" at -10.744,-55.514 h1.52
  text "GENERATED    :" at 31.75,-55.514 h1.52
  text ".Print_Date" at 53.835,-55.514 h1.52
  text ".Print_Time" at 72.352,-55.514 h1.52
  text "TEXAS INSTRUMENTS" at 104.47,-55.514 h1.52
M12 Stackup:
  drawing of 295 lines, arcs and shapes, not listed
  text "Layer" at 223.465,170.402 h1.52
  text "Name" at 233.877,170.402 h1.52
  text "Material" at 257.493,170.402 h1.52
  text "Thickness" at 280.092,170.402 h1.52
  text "Constant" at 296.598,170.402 h1.52
  text "Board Layer Stack" at 311.073,170.402 h1.52
  text "1" at 223.465,167.354 h1.52
  text "Top Overlay" at 233.877,167.354 h1.52
  text "2" at 223.465,164.306 h1.52
  text "Top Solder" at 233.877,164.306 h1.52
  text "Solder Resist" at 257.493,164.306 h1.52
  text "0.40mil" at 280.092,164.306 h1.52
  text "3.5" at 296.598,164.306 h1.52
  text "3" at 223.465,161.258 h1.52
  text "Top Layer" at 233.877,161.258 h1.52
  text "Copper" at 257.493,161.258 h1.52
  text "2.76mil" at 280.092,161.258 h1.52
  text "4" at 223.465,158.21 h1.52
  text "Dielectric 2" at 233.877,158.21 h1.52
  text "FR-4  High Tg" at 257.493,158.21 h1.52
  text "6.30mil" at 280.092,158.21 h1.52
  text "4.2" at 296.598,158.21 h1.52
  text "5" at 223.465,155.162 h1.52
  text "L2" at 233.877,155.162 h1.52
  text "Copper" at 257.493,155.162 h1.52
  text "2.76mil" at 280.092,155.162 h1.52
  text "6" at 223.465,152.114 h1.52
  text "Dielectric1" at 233.877,152.114 h1.52
  text "FR-4  High Tg" at 257.493,152.114 h1.52
  text "7.87mil" at 280.092,152.114 h1.52
  text "4.8" at 296.598,152.114 h1.52
  text "7" at 223.465,149.066 h1.52
  text "L3" at 233.877,149.066 h1.52
  text "Copper" at 257.493,149.066 h1.52
  text "2.76mil" at 280.092,149.066 h1.52
  text "8" at 223.465,146.018 h1.52
  text "Dielectric 3" at 233.877,146.018 h1.52
  text "FR-4  High Tg" at 257.493,146.018 h1.52
  text "6.30mil" at 280.092,146.018 h1.52
  text "4.2" at 296.598,146.018 h1.52
  text "9" at 223.465,142.97 h1.52
  text "Bottom Layer" at 233.877,142.97 h1.52
  text "Copper" at 257.493,142.97 h1.52
  text "2.76mil" at 280.092,142.97 h1.52
  text "10" at 223.465,139.922 h1.52
  text "Bottom Solder" at 233.877,139.922 h1.52
  text "Solder Resist" at 257.493,139.922 h1.52
  text "0.40mil" at 280.092,139.922 h1.52
  text "3.5" at 296.598,139.922 h1.52
  text "11" at 223.465,136.874 h1.52
  text "Bottom Overlay" at 233.877,136.874 h1.52
M14 Component Bodies Bottom:
  text ".Layer_Name" at -10.744,-50.286 h1.52
M15 Courtyards Top:
  text ".Layer_Name" at -10.744,-50.286 h1.52
M16 Courtyards Bottom:
  text ".Layer_Name" at -10.744,-50.286 h1.52
Drill Drawing:
  lines w0.254: 109.9,45.851 111.024,45.851 110.462,44.727 109.9,45.851 ; 109.9,47.257 111.024,47.257 111.024,48.382 109.9,48.382 109.9,47.257 ; 109.9,50.912 111.024,50.912 110.462,49.787 109.9,50.912 ; 109.9,52.599 110.181,52.599 110.462,52.318 110.743,52.599 111.024,52.599 110.743,52.88 111.024,53.161 110.743,53.161 110.462,53.443 110.181,53.161 109.9,53.161 110.181,52.88 109.9,52.599 ; 109.9,55.129 110.181,55.129 110.181,54.848 110.743,54.848 110.743,55.129 111.024,55.129 111.024,55.692 110.743,55.692 110.743,55.973 110.181,55.973 110.181,55.692 109.9,55.692 109.9,55.129 ; 110.125,50.687 110.799,50.687 110.462,50.012 110.125,50.687
  lines w0.305: 108.864,43.968 174.869,43.968 ; 108.864,56.62 174.869,56.62 ; 116.882,41.437 116.882,59.15 ; 124.938,41.437 124.938,59.15 ; 140.73,41.437 140.73,59.15 ; 146.936,41.437 146.936,59.15 ; 156.089,41.437 156.089,59.15 ; 108.864,41.437 174.869,41.437 174.869,59.15 108.864,59.15 108.864,41.437
  text "Symbol" at 110.383,57.379 h1.83
  text "Quantity" at 117.641,57.379 h1.83
  text "Finished Hole Size" at 125.697,57.379 h1.83
  text "Plated" at 141.489,57.379 h1.83
  text "Hole Type" at 147.695,57.379 h1.83
  text "Drill Layer Pair" at 156.848,57.379 h1.83
  text "5" at 117.641,54.848 h1.52
  text "7.87mil (0.200mm)" at 125.697,54.848 h1.52
  text "PTH" at 141.489,54.848 h1.52
  text "Round" at 147.695,54.848 h1.52
  text "Top Layer - Bottom Layer" at 156.848,54.848 h1.52
  text "248" at 117.641,52.318 h1.52
  text "10.00mil (0.254mm)" at 125.697,52.318 h1.52
  text "PTH" at 141.489,52.318 h1.52
  text "Round" at 147.695,52.318 h1.52
  text "Top Layer - Bottom Layer" at 156.848,52.318 h1.52
  text "14" at 117.641,49.787 h1.52
  text "25.59mil (0.650mm)" at 125.697,49.787 h1.52
  text "PTH" at 141.489,49.787 h1.52
  text "Round" at 147.695,49.787 h1.52
  text "Top Layer - Bottom Layer" at 156.848,49.787 h1.52
  text "4" at 117.641,47.257 h1.52
  text "43.31mil (1.100mm)" at 125.697,47.257 h1.52
  text "PTH" at 141.489,47.257 h1.52
  text "Round" at 147.695,47.257 h1.52
  text "Top Layer - Bottom Layer" at 156.848,47.257 h1.52
  text "5" at 117.641,44.727 h1.52
  text "51.18mil (1.300mm)" at 125.697,44.727 h1.52
  text "PTH" at 141.489,44.727 h1.52
  text "Round" at 147.695,44.727 h1.52
  text "Top Layer - Bottom Layer" at 156.848,44.727 h1.52
  text "276 Total" at 117.641,42.196 h1.52
  text "DRILL TOLERANCE" at 109.662,32.046 h1.52
  text "FOR 7.87MIL DRILL +0/- 7.87 MIL" at 111.465,26.763 h1.52
  text "FOR 10MIL DRILL +0/- 10 MIL" at 111.846,23.893 h1.52
  text "FOR PTH +/- 3 MIL" at 111.719,20.794 h1.52
  text ".Layer_Name" at -10.744,-50.286 h1.52
M17 Embedded Cavity:
  text ".Layer_Name" at -10.744,-50.286 h1.52
M18 Embedded Assembly:
  text ".Layer_Name" at -10.744,-50.286 h1.52
M19 Embedded Keepout:
  text ".Layer_Name" at -10.744,-50.286 h1.52

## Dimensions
-25.4,-38.64 to 0,-38.64 on M2 Board Dimensions
0,46 to 80,46 on M2 Board Dimensions
0,46 to 0,0 on M2 Board Dimensions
